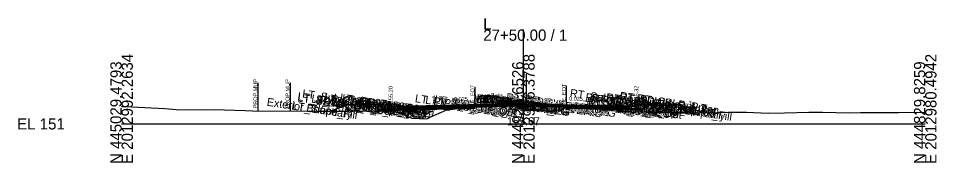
# Model space of a CAD drawing. Extents: x -26 to 4203, y -10 to 9526.
# Drawn here: x 974.3 to 1202.8, y 7490.3 to 7526.4 of the extents above; entities that cross this region are included whole.
import ezdxf

# ---------------------------------------------------------------- set-up
doc = ezdxf.new("R2010")
doc.units = 0
for name, color, linetype in [('Default', 7, 'Continuous'), ('Exist CMT Pavement', 7, 'Continuous'), ('Exist Cross Section Cell', 7, 'Continuous'), ('Exist XS Center Line Elevation Label', 7, 'Continuous'), ('Exist XS Ground Line', 7, 'Continuous'), ('Prop CMT Conc Surface', 7, 'Continuous'), ('Prop CMT Concrete Structures', 7, 'Continuous'), ('Prop CMT Pvmt Course 1', 7, 'Continuous'), ('Prop CMT Pvmt Course 1 CG', 7, 'Continuous'), ('Prop CMT Pvmt Course 1 Wedge', 7, 'Continuous'), ('Prop CMT Pvmt Course 2', 7, 'Continuous'), ('Prop CMT Pvmt Course 2 Wedge', 7, 'Continuous'), ('Prop CMT Pvmt Course 3', 7, 'Continuous'), ('Prop CMT Pvmt Course 3 Wedge', 7, 'Continuous'), ('Prop CMT Pvmt Surface', 7, 'Continuous'), ('Prop CMT Pvmt Wedge Surface 1', 7, 'Continuous'), ('Prop CMT Pvmt Wedge Surface 2', 7, 'Continuous'), ('Prop CMT Pvmt Wedge Surface 3', 7, 'Continuous'), ('Prop CMT Slope Grass', 7, 'Continuous'), ('Prop CMT Subgrade Earthwork', 7, 'Continuous'), ('Prop XS Hydro Elevations', 7, 'Continuous'), ('Prop XS Label Text', 7, 'Continuous'), ('Prop XS SE Text', 7, 'Continuous'), ('Prop XS Side Slope Text', 7, 'Continuous'), ('Scratch_Level_0', 7, 'Continuous'), ('Scratch_Level_3', 7, 'Continuous')]:
    doc.layers.add(name, color=color, linetype=linetype)

msp = doc.modelspace()

# ---------------------------------------------------------------- linework, layer by layer
at = {"layer": 'Exist CMT Pavement'}
for points in [[(1100, 7504.67), (1099.59, 7504.67), (1099.17, 7504.67), (1098.94, 7504.66), (1098.82, 7504.66), (1098.48, 7504.65), (1097.91, 7504.62), (1097.09, 7504.58), (1096.64, 7504.56), (1094.59, 7504.48), (1092.28, 7504.4), (1092.1, 7504.4), (1089.62, 7504.27), (1089.59, 7504.27), (1089.48, 7504.26), (1087.94, 7504.21)], [(1100, 7504.67), (1100.24, 7504.66), (1102.07, 7504.65), (1103.73, 7504.64), (1104.59, 7504.63), (1105.55, 7504.61), (1107.08, 7504.58), (1108.46, 7504.56), (1109.61, 7504.55), (1109.86, 7504.53), (1110.68, 7504.5), (1110.68, 7504.5)]]:
    msp.add_lwpolyline(points, dxfattribs=at)
at = {"layer": 'Exist Cross Section Cell'}
for p, q in [((1100, 7500), (1100, 7523.57)), ((1000, 7500), (1100, 7500)), ((1100, 7500), (1200, 7500))]:
    msp.add_line(p, q, dxfattribs=at)
at = {"layer": 'Exist XS Ground Line'}
msp.add_lwpolyline([(1000, 7504.34), (1000.73, 7504.32), (1004.12, 7504.19), (1010.74, 7503.81), (1013.59, 7503.6), (1020.76, 7503.53), (1023.05, 7503.56), (1030.78, 7503.31), (1032.57, 7503.29), (1048.66, 7503.19), (1051.55, 7503.19), (1055.42, 7503.19), (1063.28, 7503.26), (1067.55, 7503.29), (1069.87, 7502.4), (1072.25, 7501.44), (1074.07, 7501.36), (1075.97, 7501.3), (1077.11, 7501.84), (1080.91, 7503.51), (1083.67, 7503.81), (1086.43, 7504.1), (1086.81, 7504.13), (1087.23, 7504.16), (1087.94, 7504.21), (1089.62, 7504.27), (1092.28, 7504.4), (1094.59, 7504.48), (1096.64, 7504.56), (1097.09, 7504.58), (1097.91, 7504.62), (1098.48, 7504.65), (1098.82, 7504.66), (1099.17, 7504.67), (1099.59, 7504.67), (1100.24, 7504.66), (1102.07, 7504.65), (1103.73, 7504.64), (1104.59, 7504.63), (1105.55, 7504.61), (1107.08, 7504.58), (1108.46, 7504.56), (1109.86, 7504.53), (1110.68, 7504.5), (1112.91, 7504.31), (1114.5, 7504.18), (1116.39, 7504.01), (1123.83, 7503.16), (1124.14, 7503.13), (1125.28, 7503.11), (1126.96, 7503.07), (1140.99, 7502.87), (1146.04, 7502.8), (1151, 7502.91), (1155.5, 7502.93), (1161.02, 7502.72), (1164.96, 7502.73), (1171.04, 7502.93), (1174.42, 7502.91), (1181.06, 7502.8), (1183.88, 7502.83), (1191.08, 7502.85), (1193.34, 7502.82), (1200, 7502.95)], dxfattribs=at)
at = {"layer": 'Prop CMT Conc Surface'}
for points in [[(1132.63, 7504.91), (1137.63, 7505.01)], [(1066.98, 7504.2), (1066.98, 7504.7), (1066.48, 7504.7)], [(1068.98, 7504.33), (1066.98, 7504.2)], [(1126.12, 7504.45), (1128.12, 7504.32)], [(1128.12, 7504.32), (1128.12, 7504.82), (1128.62, 7504.82)]]:
    msp.add_lwpolyline(points, dxfattribs=at)
at = {"layer": 'Prop CMT Concrete Structures'}
for p, q in [((1095.52, 7505.16), (1095.51, 7504.99)), ((1096.27, 7505.41), (1095.52, 7505.16)), ((1098.47, 7505.53), (1096.27, 7505.41)), ((1099.99, 7505.5), (1098.47, 7505.53)), ((1100.74, 7505.25), (1099.99, 7505.5)), ((1100.75, 7505.09), (1100.74, 7505.25))]:
    msp.add_line(p, q, dxfattribs=at)
for points in [[(1095.51, 7504.99), (1100, 7505.11), (1100.75, 7505.09)], [(1137.63, 7505.01), (1132.63, 7504.91)], [(1137.63, 7504.68), (1137.63, 7505.01)], [(1068.98, 7504.33), (1066.98, 7504.2), (1066.98, 7504.7), (1066.48, 7504.7)], [(1066.48, 7504.7), (1066.48, 7503.68), (1068.98, 7503.75)], [(1068.98, 7503.75), (1068.98, 7504.33)], [(1126.12, 7504.45), (1128.12, 7504.32), (1128.12, 7504.82), (1128.62, 7504.82)], [(1128.62, 7504.82), (1128.62, 7503.81), (1126.12, 7503.87)], [(1126.12, 7503.87), (1126.12, 7504.45)], [(1132.63, 7504.91), (1132.63, 7504.58)], [(1132.63, 7504.58), (1137.63, 7504.68)]]:
    msp.add_lwpolyline(points, dxfattribs=at)
at = {"layer": 'Prop CMT Pvmt Course 1'}
for points in [[(1100, 7505.11), (1068.98, 7504.33)], [(1100, 7504.86), (1100, 7505.11)], [(1100, 7505.11), (1126.12, 7504.45)], [(1100, 7504.86), (1100, 7505.11)], [(1068.98, 7504.08), (1087.94, 7504.55)], [(1068.98, 7504.33), (1068.98, 7504.08)], [(1087.94, 7504.68), (1100, 7504.98)], [(1087.94, 7504.55), (1087.94, 7504.68)], [(1100, 7504.98), (1100, 7504.86), (1100, 7504.86)], [(1110.68, 7504.71), (1100, 7504.98)], [(1100, 7504.98), (1100, 7504.86), (1100, 7504.86)], [(1110.68, 7504.59), (1110.68, 7504.71)], [(1126.12, 7504.2), (1110.68, 7504.59)], [(1126.12, 7504.45), (1126.12, 7504.2)]]:
    msp.add_lwpolyline(points, dxfattribs=at)
at = {"layer": 'Prop CMT Pvmt Course 1 CG'}
for points in [[(1068.98, 7503.75), (1065.98, 7503.67), (1065.64, 7503.33)], [(1065.64, 7503.33), (1068.98, 7503.41)], [(1068.98, 7503.41), (1068.98, 7503.75)], [(1126.12, 7503.87), (1129.12, 7503.79), (1129.46, 7503.45)], [(1126.12, 7503.54), (1126.12, 7503.87)], [(1129.46, 7503.45), (1126.12, 7503.54)]]:
    msp.add_lwpolyline(points, dxfattribs=at)
at = {"layer": 'Prop CMT Pvmt Course 1 Wedge'}
for points in [[(1087.94, 7504.68), (1089.48, 7504.72), (1089.59, 7504.72), (1089.62, 7504.72), (1092.1, 7504.78), (1092.28, 7504.79), (1094.59, 7504.85), (1096.64, 7504.9), (1097.09, 7504.91), (1097.91, 7504.93), (1098.48, 7504.94), (1098.82, 7504.95), (1098.94, 7504.95), (1099.17, 7504.96), (1099.59, 7504.97), (1100, 7504.98)], [(1100, 7504.86), (1099.59, 7504.85), (1099.17, 7504.84), (1098.94, 7504.83), (1098.82, 7504.83), (1098.48, 7504.82), (1097.91, 7504.8), (1097.09, 7504.78), (1096.64, 7504.77), (1094.59, 7504.72), (1092.28, 7504.66), (1092.1, 7504.66), (1089.62, 7504.6), (1089.59, 7504.6), (1089.48, 7504.59), (1087.94, 7504.55)], [(1087.94, 7504.55), (1087.94, 7504.68)], [(1100, 7504.98), (1100, 7504.86)], [(1100, 7504.98), (1100.24, 7504.98), (1102.07, 7504.93), (1103.73, 7504.89), (1104.59, 7504.87), (1105.55, 7504.84), (1107.08, 7504.8), (1108.46, 7504.77), (1109.61, 7504.74), (1109.86, 7504.73), (1110.68, 7504.71), (1110.68, 7504.71)], [(1100, 7504.86), (1100, 7504.98)], [(1110.68, 7504.59), (1110.68, 7504.59), (1109.86, 7504.61), (1109.61, 7504.62), (1108.46, 7504.64), (1107.08, 7504.68), (1105.55, 7504.72), (1104.59, 7504.74), (1103.73, 7504.76), (1102.07, 7504.8), (1100.24, 7504.85), (1100, 7504.86)], [(1110.68, 7504.71), (1110.68, 7504.59)]]:
    msp.add_lwpolyline(points, dxfattribs=at)
at = {"layer": 'Prop CMT Pvmt Course 2'}
for points in [[(1087.94, 7504.55), (1068.98, 7504.08)], [(1068.98, 7503.75), (1087.94, 7504.22)], [(1068.98, 7504.08), (1068.98, 7503.75)], [(1087.94, 7504.22), (1087.94, 7504.55)], [(1110.68, 7504.26), (1110.68, 7504.59)], [(1110.68, 7504.59), (1126.12, 7504.2)], [(1126.12, 7503.87), (1110.68, 7504.26)], [(1126.12, 7504.2), (1126.12, 7503.87)]]:
    msp.add_lwpolyline(points, dxfattribs=at)
at = {"layer": 'Prop CMT Pvmt Course 2 Wedge'}
for points in [[(1087.94, 7504.55), (1089.48, 7504.59), (1089.59, 7504.6), (1089.62, 7504.6), (1092.1, 7504.66), (1092.28, 7504.66), (1094.59, 7504.72), (1096.64, 7504.77), (1097.09, 7504.78), (1097.91, 7504.8), (1098.48, 7504.82), (1098.82, 7504.83), (1098.94, 7504.83), (1099.17, 7504.84), (1099.59, 7504.85), (1100, 7504.86)], [(1100, 7504.67), (1099.59, 7504.67), (1099.17, 7504.67), (1098.94, 7504.66), (1098.82, 7504.66), (1098.48, 7504.65), (1097.91, 7504.62), (1097.09, 7504.58), (1096.64, 7504.56), (1094.59, 7504.48), (1092.28, 7504.4), (1092.1, 7504.4), (1089.62, 7504.27), (1089.59, 7504.27), (1089.48, 7504.26), (1089.18, 7504.25), (1087.94, 7504.22)], [(1087.94, 7504.22), (1087.94, 7504.55)], [(1100, 7504.86), (1100.24, 7504.85), (1102.07, 7504.8), (1103.73, 7504.76), (1104.59, 7504.74), (1105.55, 7504.72), (1107.08, 7504.68), (1108.46, 7504.64), (1109.61, 7504.62), (1109.86, 7504.61), (1110.68, 7504.59), (1110.68, 7504.59)], [(1100, 7504.67), (1100, 7504.86)], [(1100, 7504.86), (1100, 7504.67)], [(1110.68, 7504.5), (1110.68, 7504.5), (1109.86, 7504.53), (1109.61, 7504.55), (1108.46, 7504.56), (1107.08, 7504.58), (1105.55, 7504.61), (1104.59, 7504.63), (1103.73, 7504.64), (1102.07, 7504.65), (1100.24, 7504.66), (1100, 7504.67)], [(1110.68, 7504.59), (1110.68, 7504.5)]]:
    msp.add_lwpolyline(points, dxfattribs=at)
at = {"layer": 'Prop CMT Pvmt Course 3'}
for points in [[(1087.94, 7504.22), (1068.98, 7503.75)], [(1068.98, 7503.41), (1087.94, 7503.89)], [(1068.98, 7503.75), (1068.98, 7503.41)], [(1087.94, 7503.89), (1087.94, 7504.22)], [(1110.68, 7504.26), (1126.12, 7503.87)], [(1110.68, 7503.92), (1110.68, 7504.26)], [(1126.12, 7503.54), (1110.68, 7503.92)], [(1126.12, 7503.87), (1126.12, 7503.54)]]:
    msp.add_lwpolyline(points, dxfattribs=at)
at = {"layer": 'Prop CMT Pvmt Course 3 Wedge'}
for points in [[(1087.94, 7504.22), (1089.2, 7504.25)], [(1089.2, 7504.25), (1087.94, 7504.21)], [(1087.94, 7504.21), (1087.94, 7504.22)]]:
    msp.add_lwpolyline(points, dxfattribs=at)
at = {"layer": 'Prop CMT Pvmt Surface'}
for points in [[(1100, 7505.11), (1068.98, 7504.33)], [(1100, 7505.11), (1126.12, 7504.45)]]:
    msp.add_lwpolyline(points, dxfattribs=at)
at = {"layer": 'Prop CMT Pvmt Wedge Surface 1'}
for points in [[(1087.94, 7504.55), (1068.98, 7504.08)], [(1068.98, 7504.08), (1068.98, 7504.33)], [(1100, 7504.98), (1087.94, 7504.68)], [(1087.94, 7504.68), (1087.94, 7504.55)], [(1100, 7504.98), (1110.68, 7504.71)], [(1110.68, 7504.71), (1110.68, 7504.59)], [(1110.68, 7504.59), (1126.12, 7504.2)], [(1126.12, 7504.2), (1126.12, 7504.45)]]:
    msp.add_lwpolyline(points, dxfattribs=at)
at = {"layer": 'Prop CMT Pvmt Wedge Surface 2'}
for points in [[(1100, 7504.86), (1068.98, 7504.08)], [(1068.98, 7504.08), (1068.98, 7504.33)], [(1100, 7504.86), (1126.12, 7504.2)], [(1126.12, 7504.2), (1126.12, 7504.45)]]:
    msp.add_lwpolyline(points, dxfattribs=at)
at = {"layer": 'Prop CMT Pvmt Wedge Surface 3'}
for points in [[(1100, 7504.52), (1068.98, 7503.75)], [(1068.98, 7503.75), (1068.98, 7504.33)], [(1100, 7504.52), (1126.12, 7503.87)], [(1126.12, 7503.87), (1126.12, 7504.45)]]:
    msp.add_lwpolyline(points, dxfattribs=at)
at = {"layer": 'Prop CMT Slope Grass'}
for points in [[(1128.62, 7504.82), (1138.12, 7505.01), (1144.71, 7502.82)], [(1066.48, 7504.7), (1056.98, 7504.89), (1051.88, 7503.19)]]:
    msp.add_lwpolyline(points, dxfattribs=at)
at = {"layer": 'Prop CMT Subgrade Earthwork'}
for points in [[(1068.98, 7503.41), (1065.64, 7503.33), (1064.23, 7504.75)], [(1087.94, 7503.89), (1068.98, 7503.41)], [(1087.94, 7503.89), (1087.94, 7504.21)], [(1110.68, 7503.92), (1110.68, 7504.5)], [(1110.68, 7503.92), (1126.12, 7503.54)], [(1126.12, 7503.54), (1129.46, 7503.45), (1130.88, 7504.87)]]:
    msp.add_lwpolyline(points, dxfattribs=at)
at = {"layer": 'Prop XS Label Text'}
for p, q in [((1033.89, 7510.28), (1033.89, 7503.28)), ((1041.91, 7510.23), (1041.91, 7503.23)), ((1087.94, 7509.21), (1087.94, 7504.21)), ((1110.68, 7509.5), (1110.68, 7504.5))]:
    msp.add_line(p, q, dxfattribs=at)
at = {"layer": 'Scratch_Level_3'}
msp.add_line((1100.75, 7505.09), (1100.75, 7512.41), dxfattribs=at)

# ---------------------------------------------------------------- texts
at = {"layer": 'Default'}
msp.add_text('-', height=0.0001, dxfattribs=at).set_placement((1000, 7500))
at = {"layer": 'Exist Cross Section Cell'}
for s, p in [('L', (1090, 7523.57)), ('27+50.00 / 1', (1090, 7520.77)), ('EL 151', (974, 7498.6))]:
    msp.add_text(s, height=2.8, dxfattribs=at).set_placement(p)
for s, p in [('E 2012992.2634', (1002.8, 7490)), ('E 2012986.3788', (1102.8, 7490)), ('E 2012980.4942', (1202.8, 7490)), ('N 445029.4793', (1000, 7490)), ('N 444929.6526', (1100, 7490)), ('N 444829.8259', (1200, 7490))]:
    msp.add_text(s, height=2.8, rotation=90, dxfattribs=at).set_placement(p)
at = {"layer": 'Exist XS Center Line Elevation Label'}
msp.add_text('155.67', height=2, dxfattribs=at).set_placement((1095.94, 7499.67))
at = {"layer": 'Prop XS Hydro Elevations'}
for s, p in [('155.20', (1067.48, 7505.2)), ('155.32', (1128.62, 7505.32))]:
    msp.add_text(s, height=1, rotation=90, dxfattribs=at).set_placement(p)
at = {"layer": 'Prop XS Label Text'}
for s, p in [('PROP.MUP', (1033.79, 7503.85)), ('PROP.MUP', (1041.81, 7503.8)), ('E. EOT', (1087.84, 7505.23)), ('E. EOT', (1110.58, 7505.52))]:
    msp.add_text(s, height=1, rotation=90, dxfattribs=at).set_placement(p)
at = {"layer": 'Prop XS SE Text'}
for rotation, p in [(1.4332, (1082.73, 7505.67)), (358.568, (1111.35, 7505.82))]:
    msp.add_text('0.025', height=1, rotation=rotation, dxfattribs=at).set_placement(p)
at = {"layer": 'Prop XS Side Slope Text'}
for rotation, p in [(18.4288, (1053.44, 7504.5)), (341.5609, (1140.9, 7504.88))]:
    msp.add_text('3:1', height=1, rotation=rotation, dxfattribs=at).set_placement(p)
at = {"layer": 'Scratch_Level_0'}
for s, p in [('LT_SDWK_Out_Top', (1043.67, 7505.94)), ('LT_SDWK_Out_Bot', (1043.7, 7505.61)), ('LT_Sub_Trench_Out_DLT', (1044.86, 7506.64)), ('LT_CSLP_Pnt', (1047.12, 7505.36)), ('LT_SDWK_In_Top', (1050.27, 7505.6)), ('LT_CG_Top_Face', (1054.24, 7505.6)), ('LT_CG_Top_BOC', (1054.75, 7505.45)), ('LT_PV_Sub_Tie_Out', (1072.92, 7505.45)), ('MI_Face In', (1087.35, 7505.37)), ('RT_PV_IEEOP_EG', (1088.12, 7505.44)), ('LT_PV_IEEOP_EG', (1088.17, 7505.43)), ('MI_Top In', (1089.05, 7505.48)), ('RT_PV2_IEEOP', (1089.87, 7505.36)), ('LT_PV2_IEEOP', (1089.92, 7505.36)), ('27+50.00', (1090.37, 7505.48)), ('RT_PV1_IEEOP', (1090.43, 7505.41)), ('LT_PV1_IEEOP', (1090.48, 7505.4)), ('MI_Crown', (1091.42, 7505.57)), ('MI_Face Out', (1091.56, 7505.69)), ('MI_Top Out', (1091.76, 7505.8)), ('MI_Bot Out', (1092.55, 7505.38)), ('RT_PV_Sub_Tie_Out', (1095.58, 7505.75)), ('RT_PV_OEEOP_EG', (1098.16, 7505.36)), ('RT_Sub_Trench_Out_DLT', (1111.47, 7506.77)), ('RT_CG_Top_Face', (1115.33, 7505.73)), ('RT_CG_Top_BOC', (1116.84, 7505.58)), ('RT_SDWK_In_Top', (1120.43, 7505.73)), ('RT_SDWK_In_Bot', (1120.46, 7505.39)), ('RT_SDWK_Out_Top', (1123.82, 7506.07)), ('RT_SDWK_Out_Bot', (1123.85, 7505.74)), ('RT_CSLP_Pnt', (1128.21, 7505.49)), ('Exterior Boundary', (1036.04, 7504.55)), ('LT_Slope_Fill', (1042.35, 7503.61)), ('27+50.00', (1047.8, 7504.12)), ('LT_SDWK_In_Bot', (1050.3, 7505.27)), ('LT_CG1_Shelf_Out', (1052.54, 7504.68)), ('27+50.00', (1053.2, 7504.85)), ('LT_CG_Bot_BOC', (1054.78, 7504.43)), ('LT_CG_Top_Gut', (1055.2, 7504.96)), ('LT_Sub_OEOP', (1055.71, 7503.81)), ('27+50.00', (1058.09, 7504.75)), ('LT_CG_Bot_IE', (1058.86, 7504.25)), ('LT_Sub_OEOT', (1059.02, 7503.9)), ('LT_PV2_OEOT', (1059.12, 7504.55)), ('LT_PV3_OEOT', (1059.12, 7504.22)), ('LT_PV1_OEOT', (1059.68, 7504.71)), ('27+50.00', (1059.81, 7504.71)), ('27+50.00', (1062.86, 7504.36)), ('LT_PV_OEEOP_EG', (1075.48, 7505.07)), ('LT_Sub_OEEOP', (1077.13, 7504.5)), ('LT_PV2_OEEOP', (1077.22, 7505.15)), ('LT_PV3_OEEOP', (1077.22, 7504.82)), ('LT_PV1_OEEOP', (1077.78, 7505.19)), ('MI_Bot In', (1088.32, 7505.06)), ('27+50.00', (1088.68, 7505.04)), ('27+50.00', (1089.11, 7505.31)), ('RT_PV3_IEEOP', (1089.87, 7505.03)), ('LT_PV3_IEEOP', (1089.92, 7505.02)), ('PV2_PGL', (1093.82, 7504.77)), ('PV1_PGL', (1094.38, 7504.94)), ('MI_Bot', (1095.09, 7504.83)), ('RT_Sub_OEEOP', (1099.81, 7504.54)), ('RT_PV2_OEEOP', (1099.91, 7505.19)), ('RT_PV3_OEEOP', (1099.91, 7504.86)), ('RT_PV1_OEEOP', (1100.47, 7505.23)), ('RT_CG1_Shelf_Out', (1115.63, 7504.81)), ('RT_CG_Bot_IE', (1115.95, 7504.38)), ('RT_Sub_OEOT', (1116.12, 7504.03)), ('RT_PV2_OEOT', (1116.21, 7504.68)), ('RT_PV3_OEOT', (1116.21, 7504.34)), ('RT_CG_Top_Gut', (1116.29, 7505.09)), ('RT_PV1_OEOT', (1116.77, 7504.84)), ('RT_CG_Bot_BOC', (1116.87, 7504.56)), ('RT_Sub_OEOP', (1119.49, 7503.94)), ('27+50.00', (1121.35, 7504.84)), ('27+50.00', (1123.18, 7504.86)), ('27+50.00', (1127.66, 7504.96)), ('Exterior Boundary', (1128.88, 7504.18)), ('RT_Slope_Fill', (1135.14, 7503.24)), ('27+50.00', (1136.45, 7503.31))]:
    msp.add_text(s, height=2, rotation=351.4697, dxfattribs=at).set_placement(p)

doc.saveas('drawing.dxf')
